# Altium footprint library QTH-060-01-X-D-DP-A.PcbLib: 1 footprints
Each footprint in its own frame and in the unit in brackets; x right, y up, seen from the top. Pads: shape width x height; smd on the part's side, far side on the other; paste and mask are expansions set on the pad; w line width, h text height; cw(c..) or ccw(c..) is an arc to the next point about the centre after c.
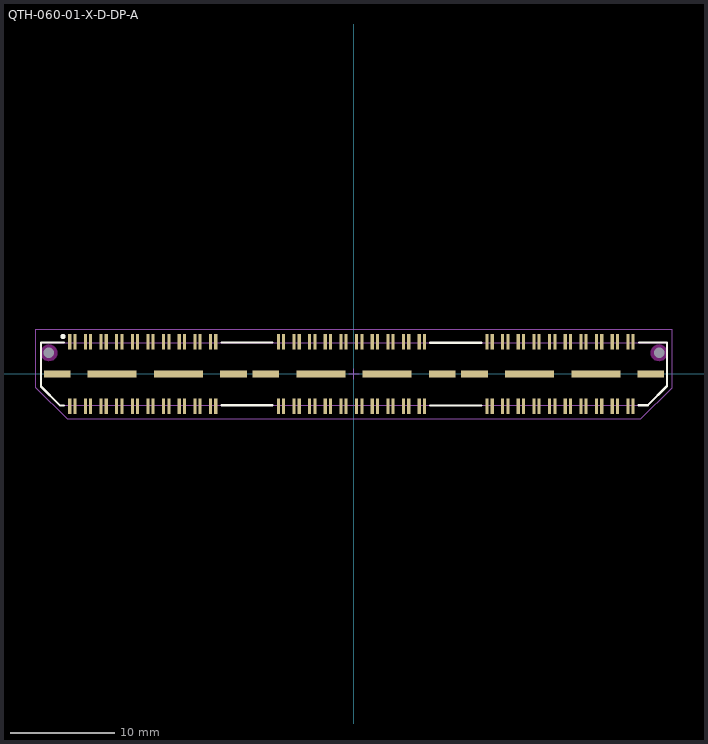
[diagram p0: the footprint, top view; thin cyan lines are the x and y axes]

## QTH-060-01-X-D-DP-A [mm] "0.50mm pitch, 120 pin, high speed terminal strip; differential"
height 4.27
pads (134):
  rect 0.3x1.45 smd mask+0: 1(-27.25,3.09) 2(-27.25,-3.09) 3(-26.75,3.09) 4(-26.75,-3.09) 5(-25.75,3.09) 6(-25.75,-3.09) 7(-25.25,3.09) 8(-25.25,-3.09) 9(-24.25,3.09) 10(-24.25,-3.09) 11(-23.75,3.09) 12(-23.75,-3.09) 13(-22.75,3.09) 14(-22.75,-3.09) 15(-22.25,3.09) 16(-22.25,-3.09) 17(-21.25,3.09) 18(-21.25,-3.09) 19(-20.75,3.09) 20(-20.75,-3.09) 21(-19.75,3.09) 22(-19.75,-3.09) 23(-19.25,3.09) 24(-19.25,-3.09) 25(-18.25,3.09) 26(-18.25,-3.09) 27(-17.75,3.09) 28(-17.75,-3.09) 29(-16.75,3.09) 30(-16.75,-3.09) 31(-16.25,3.09) 32(-16.25,-3.09) 33(-15.25,3.09) 34(-15.25,-3.09) 35(-14.75,3.09) 36(-14.75,-3.09) 37(-13.75,3.09) 38(-13.75,-3.09) 39(-13.25,3.09) 40(-13.25,-3.09) 41(-7.25,3.09) 42(-7.25,-3.09) 43(-6.75,3.09) 44(-6.75,-3.09) 45(-5.75,3.09) 46(-5.75,-3.09) 47(-5.25,3.09) 48(-5.25,-3.09) 49(-4.25,3.09) 50(-4.25,-3.09) 51(-3.75,3.09) 52(-3.75,-3.09) 53(-2.75,3.09) 54(-2.75,-3.09) 55(-2.25,3.09) 56(-2.25,-3.09) 57(-1.25,3.09) 58(-1.25,-3.09) 59(-0.75,3.09) 60(-0.75,-3.09) 61(0.25,3.09) 62(0.25,-3.09) 63(0.75,3.09) 64(0.75,-3.09) 65(1.75,3.09) 66(1.75,-3.09) 67(2.25,3.09) 68(2.25,-3.09) 69(3.25,3.09) 70(3.25,-3.09) 71(3.75,3.09) 72(3.75,-3.09) 73(4.75,3.09) 74(4.75,-3.09) 75(5.25,3.09) 76(5.25,-3.09) 77(6.25,3.09) 78(6.25,-3.09) 79(6.75,3.09) 80(6.75,-3.09) 81(12.75,3.09) 82(12.75,-3.09) 83(13.25,3.09) 84(13.25,-3.09) 85(14.25,3.09) 86(14.25,-3.09) 87(14.75,3.09) 88(14.75,-3.09) 89(15.75,3.09) 90(15.75,-3.09) 91(16.25,3.09) 92(16.25,-3.09) 93(17.25,3.09) 94(17.25,-3.09) 95(17.75,3.09) 96(17.75,-3.09) 97(18.75,3.09) 98(18.75,-3.09) 99(19.25,3.09) 100(19.25,-3.09) 101(20.25,3.09) 102(20.25,-3.09) 103(20.75,3.09) 104(20.75,-3.09) 105(21.75,3.09) 106(21.75,-3.09) 107(22.25,3.09) 108(22.25,-3.09) 109(23.25,3.09) 110(23.25,-3.09) 111(23.75,3.09) 112(23.75,-3.09) 113(24.75,3.09) 114(24.75,-3.09) 115(25.25,3.09) 116(25.25,-3.09) 117(26.25,3.09) 118(26.25,-3.09) 119(26.75,3.09) 120(26.75,-3.09)
  rect 2.55x0.65 smd mask+0: 121(-28.445,0) 124(-11.555,0) 125(-8.445,0) 128(8.445,0) 129(11.555,0) 132(28.445,0)
  rect 4.7x0.65 smd mask+0: 122(-23.175,0) 123(-16.825,0) 126(-3.175,0) 127(3.175,0) 130(16.825,0) 131(23.175,0)
  round 0.5 hole 1 unplated mask+0: 133(-29.24,2.03) 134(29.24,2.03)
Top Overlay:
  circle w0.25: c-27.9,3.6 r0.125
  lines w0.2: -27.801,-3.004 -28.196,-3.004 -29.998,-1.203 -29.998,3.001 -27.801,3.001 ; -12.718,3.003 -7.801,3.003 ; -12.711,-2.998 -7.794,-2.998 ; 7.293,2.999 12.206,2.999 ; 7.3,-3.008 12.2,-3.008 ; 27.298,-2.997 28.162,-2.997 30.004,-1.156 30.004,3.001 27.302,3.001
Keep-Out Layer:
  pour cut-out: -28.433,2.03 -28.461,2.239 -28.541,2.433 -28.669,2.601 -28.837,2.729 -29.031,2.809 -29.24,2.837 -29.449,2.809 -29.643,2.729 -29.811,2.601 -29.939,2.433 -30.019,2.239 -30.047,2.03 -30.019,1.821 -29.939,1.627 -29.811,1.459 -29.643,1.331 -29.449,1.251 -29.24,1.223 -29.031,1.251 -28.837,1.331 -28.669,1.459 -28.541,1.627 -28.461,1.821
  pour cut-out: 30.047,2.03 30.019,2.239 29.939,2.433 29.811,2.601 29.643,2.729 29.449,2.809 29.24,2.837 29.031,2.809 28.837,2.729 28.669,2.601 28.541,2.433 28.461,2.239 28.433,2.03 28.461,1.821 28.541,1.627 28.669,1.459 28.837,1.331 29.031,1.251 29.24,1.223 29.449,1.251 29.643,1.331 29.811,1.459 29.939,1.627 30.019,1.821
Mechanical 12:
  lines w0.001: -30,-1.2 -28.2,-3 28.15,-3 30,-1.15 30,3 -30,3 -30,-1.2
Mechanical 13:
  lines w0.1: -30,-1.2 -28.2,-3 28.15,-3 30,-1.15 30,3 -30,3 -30,-1.2
  text ".Designator" at 0.127,-0.127 h1.52
Mechanical 15:
  lines w0.05: -0.5,0 0.5,0 ; 0,-0.5 0,0.5 ; -30.5,-1.3 -27.5,-4.3 27.5,-4.3 30.5,-1.3 30.5,4.3 -30.5,4.3 -30.5,-1.3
